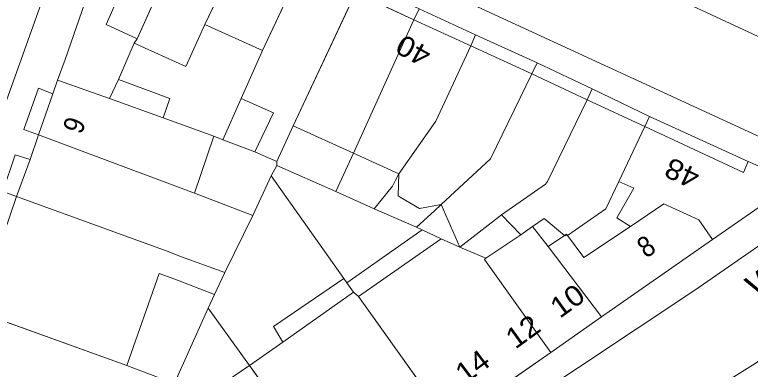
# Model space of a CAD drawing. Extents: x 528790 to 529292, y 179350 to 179856.
# Drawn here: x 529183.9 to 529237.6, y 179393.9 to 179419.8 of the extents above; entities that cross this region are included whole.
import ezdxf

# ---------------------------------------------------------------- set-up
doc = ezdxf.new("R2010")
doc.units = 0
doc.header["$LTSCALE"] = 0.6
doc.layers.add('1', color=7, linetype='Continuous', lineweight=13)
doc.layers.add('2', color=7, linetype='Continuous', lineweight=13)
doc.layers.add('5', color=7, linetype='Continuous')

msp = doc.modelspace()

# ---------------------------------------------------------------- linework, layer by layer
at = {"layer": '1'}
for points in [[(529152.592, 179458.708), (529152.53, 179458.27), (529152.737, 179457.756), (529153.247, 179457.24), (529154.075, 179456.846), (529157.2, 179455.4), (529168.6, 179450.1), (529184.6, 179442.9), (529186.46, 179442.05), (529193.12, 179438.98), (529195.7, 179437.8), (529210.8, 179430.8), (529226.95, 179423.45), (529240.8, 179417)], [(529242.05, 179409.15), (529191.35, 179432.55)], [(529181.6, 179428.5), (529176.4, 179414.3), (529171.5, 179401.3), (529167.35, 179390.15), (529162.35, 179376.4), (529162.05, 179375.9), (529161.9, 179375.7), (529161.6, 179375.55), (529161.25, 179375.45), (529169.115, 179372.981), (529169.121, 179373.036), (529169.129, 179373.091), (529169.131, 179373.129), (529169.2, 179374.196), (529169.204, 179374.262), (529169.205, 179374.273), (529189.9, 179432.1)], [(529189.9, 179432.1), (529169.205, 179374.273)], [(529183.1, 179403.9), (529184, 179406.55), (529183, 179406.9), (529183.9, 179409.6), (529185, 179409.25), (529185.6, 179411.05), (529184.55, 179411.45), (529185.6, 179414.45), (529186.65, 179414.05), (529187, 179415.05), (529187.55, 179416.55), (529189.4, 179421.9)], [(529213.4, 179420.25), (529217.5, 179418.35), (529222, 179416.3), (529226, 179414.4), (529230.2, 179412.4), (529237.4, 179409.1), (529239.25, 179408.3)], [(529239.4, 179406.6), (529234.8, 179403.4), (529226.7, 179397.75), (529223, 179395.15), (529215.55, 179390), (529215.2, 179389.8), (529207.9, 179384.7), (529204, 179382.05), (529200.3, 179379.5), (529196.4, 179376.8), (529193, 179374.5), (529189.15, 179371.8), (529183.05, 179370.6)], [(529195.35, 179374.3), (529233.5, 179399.7), (529242.15, 179405.7)], [(529242.15, 179405.7), (529233.5, 179399.7), (529195.35, 179374.3)], [(529237.9, 179394.35), (529233.9, 179391.85)], [(529233.9, 179391.85), (529237.9, 179394.35)]]:
    msp.add_lwpolyline(points, dxfattribs=at)
for points in [[(529190.2, 179432.45), (529190.55, 179432.55), (529190.8, 179432.65), (529191.05, 179432.65), (529191.35, 179432.55), (529242.05, 179409.15), (529242.35, 179408.85), (529242.6, 179408.15), (529250, 179413.05), (529240.8, 179417), (529226.95, 179423.45), (529210.8, 179430.8), (529195.7, 179437.8), (529193.12, 179438.98)], [(529192.8, 179418.05), (529196.8, 179427), (529192, 179429.25), (529189.4, 179421.9), (529191.4, 179421.05), (529190.55, 179419.1)], [(529192.6, 179417.75), (529196.35, 179416.05), (529197.75, 179419.1), (529200.65, 179425.2), (529196.8, 179427), (529192.8, 179418.05)], [(529201.95, 179417.2), (529204.8, 179423.3), (529200.65, 179425.2), (529197.75, 179419.1)], [(529208.75, 179421.45), (529204.8, 179423.3), (529201.95, 179417.2), (529200.4, 179413.7), (529202.75, 179412.65), (529201.4, 179409.8), (529203, 179409.1), (529204.2, 179411.7)], [(529208.75, 179421.45), (529213, 179419.45), (529213.4, 179420.25), (529209.15, 179422.25)], [(529191.45, 179415.1), (529192.6, 179417.75), (529192.8, 179418.05), (529190.55, 179419.1), (529191.4, 179421.05), (529189.4, 179421.9), (529187.55, 179416.55), (529187, 179415.05), (529190.8, 179413.7)], [(529204.2, 179411.7), (529208.6, 179409.7), (529213, 179419.45), (529208.75, 179421.45)], [(529213.4, 179420.25), (529213, 179419.45), (529217.15, 179417.55), (529217.5, 179418.35)], [(529211.9, 179408.2), (529214.6, 179412.05), (529217.15, 179417.55), (529213, 179419.45), (529208.6, 179409.7)], [(529199.07, 179410.69), (529200.4, 179413.7), (529201.95, 179417.2), (529197.75, 179419.1), (529196.35, 179416.05), (529192.6, 179417.75), (529191.45, 179415.1), (529195.2, 179413.7), (529194.95, 179413), (529194.7, 179412.3), (529198.4, 179410.95)], [(529217.15, 179417.55), (529221.6, 179415.5), (529222, 179416.3), (529217.5, 179418.35)], [(529215, 179405.95), (529218.6, 179409.3), (529221.6, 179415.5), (529217.15, 179417.55), (529214.6, 179412.05), (529211.9, 179408.2), (529211.852, 179406.591), (529211.935, 179406.541), (529212.004, 179406.5), (529213.41, 179405.659)], [(529226, 179414.4), (529222, 179416.3), (529221.6, 179415.5), (529225.65, 179413.6)], [(529219.4, 179405.2), (529222.6, 179407.45), (529222.75, 179407.65), (529225.65, 179413.6), (529221.6, 179415.5), (529218.6, 179409.3), (529215, 179405.95), (529216.35, 179402.85)], [(529187, 179415.05), (529186.65, 179414.05), (529185.6, 179411.05), (529197, 179406.8), (529198.4, 179410.95), (529194.7, 179412.3), (529190.8, 179413.7)], [(529191.45, 179415.1), (529190.8, 179413.7), (529194.7, 179412.3), (529194.95, 179413), (529195.2, 179413.7)], [(529186.65, 179414.05), (529185.6, 179414.45), (529184.55, 179411.45), (529185.6, 179411.05)], [(529226, 179414.4), (529225.65, 179413.6), (529229.85, 179411.65), (529230.2, 179412.4)], [(529202.75, 179412.65), (529200.4, 179413.7), (529199.07, 179410.69), (529201.4, 179409.8)], [(529221.65, 179404.35), (529222.5, 179404.95), (529224, 179403.7), (529224.15, 179403.8), (529224.2, 179403.7), (529227, 179405.65), (529227.95, 179407.65), (529229.85, 179411.65), (529225.65, 179413.6), (529222.75, 179407.65), (529222.6, 179407.45), (529219.4, 179405.2), (529220.8, 179403.75)], [(529237.4, 179409.1), (529230.2, 179412.4), (529229.85, 179411.65), (529237.05, 179408.3)], [(529203, 179409.1), (529203, 179408.8), (529207.3, 179406.9), (529208.6, 179409.7), (529204.2, 179411.7)], [(529237.4, 179409.1), (529237.05, 179408.3), (529229.85, 179411.65), (529227.95, 179407.65), (529229.05, 179407.15), (529227.8, 179405), (529228.8, 179404.35), (529231.25, 179406), (529233.8, 179404.85), (529234.8, 179403.4), (529239.4, 179406.6), (529239.25, 179408.3)], [(529199.2, 179401), (529201.25, 179405.15), (529197, 179406.8), (529185.6, 179411.05), (529185, 179409.25), (529184, 179406.55), (529195, 179402.55), (529196.05, 179402.15)], [(529202.6, 179408.05), (529203, 179408.8), (529203, 179409.1), (529201.4, 179409.8), (529199.07, 179410.69), (529198.4, 179410.95), (529197, 179406.8), (529201.25, 179405.15)], [(529185, 179409.25), (529183.9, 179409.6), (529183, 179406.9), (529184, 179406.55)], [(529211.45, 179407.3), (529211.668, 179407.736), (529211.9, 179408.2), (529208.6, 179409.7), (529207.3, 179406.9), (529210.1, 179405.65)], [(529208.1, 179400.25), (529213.6, 179404.1), (529213.2, 179404.3), (529210.1, 179405.65), (529207.3, 179406.9), (529203, 179408.8), (529202.6, 179408.05), (529207.9, 179400.55)], [(529213.2, 179404.3), (529214.504, 179405.495), (529215, 179405.95), (529213.41, 179405.659), (529212.004, 179406.5), (529211.935, 179406.541), (529211.852, 179406.591), (529211.9, 179408.2), (529211.668, 179407.736), (529211.45, 179407.3), (529210.1, 179405.65)], [(529203.45, 179395.9), (529202.75, 179397.05), (529205.29, 179398.78), (529207.9, 179400.55), (529202.6, 179408.05), (529201.25, 179405.15), (529199.2, 179401), (529198.45, 179399.4), (529198, 179398.4), (529201, 179394.2)], [(529228.8, 179404.35), (529227.8, 179405), (529229.05, 179407.15), (529227.95, 179407.65), (529227, 179405.65), (529224.2, 179403.7), (529225.4, 179402.1)], [(529192.05, 179394.2), (529194.427, 179400.927), (529195.55, 179400.501), (529198.45, 179399.4), (529199.2, 179401), (529196.05, 179402.15), (529195, 179402.55), (529184, 179406.55), (529183.1, 179403.9), (529181.1, 179398.15)], [(529216.35, 179402.85), (529215, 179405.95), (529214.504, 179405.495), (529213.2, 179404.3), (529213.6, 179404.1), (529215, 179403.45)], [(529226.7, 179397.75), (529234.8, 179403.4), (529233.8, 179404.85), (529231.25, 179406), (529228.8, 179404.35), (529225.4, 179402.1), (529224.2, 179403.7), (529224.1, 179403.67), (529224, 179403.7), (529222.8, 179402.9)], [(529218.25, 179402.05), (529220.8, 179403.75), (529219.4, 179405.2), (529216.35, 179402.85)], [(529222.8, 179402.9), (529224, 179403.7), (529222.5, 179404.95), (529221.65, 179404.35)], [(529208.6, 179399.55), (529208.95, 179399.25), (529215, 179403.45), (529213.6, 179404.1), (529208.1, 179400.25)], [(529221.65, 179404.35), (529220.8, 179403.75), (529218.25, 179402.05), (529218.15, 179401.95), (529223, 179395.15), (529226.7, 179397.75), (529222.8, 179402.9)], [(529208.95, 179399.25), (529215.55, 179390), (529223, 179395.15), (529218.15, 179401.95), (529218.25, 179402.05), (529216.35, 179402.85), (529215, 179403.45)], [(529224.2, 179403.7), (529224.15, 179403.8), (529224, 179403.7), (529224.1, 179403.67)], [(529195.75, 179393.4), (529198, 179398.4), (529198.45, 179399.4), (529195.55, 179400.501), (529194.427, 179400.927), (529192.05, 179394.2), (529195.5, 179392.9)], [(529208.1, 179400.25), (529207.9, 179400.55), (529205.29, 179398.78), (529202.75, 179397.05), (529203.45, 179395.9), (529208.6, 179399.55)], [(529215.55, 179390), (529208.95, 179399.25), (529208.6, 179399.55), (529203.45, 179395.9), (529201, 179394.2), (529207.9, 179384.7), (529215.2, 179389.8)], [(529194.322, 179390.628), (529195.5, 179392.9), (529192.05, 179394.2), (529181.1, 179398.15), (529180.5, 179396.45), (529179.5, 179393.65), (529189, 179390.3), (529193.4, 179388.85)], [(529200.033, 179391.89), (529199.25, 179393), (529201, 179394.2), (529198, 179398.4), (529195.75, 179393.4), (529197.901, 179390.415)], [(529207.9, 179384.7), (529201, 179394.2), (529199.25, 179393), (529200.033, 179391.89), (529197.901, 179390.415), (529198.2, 179390), (529199.35, 179388.55), (529200.019, 179387.614), (529204, 179382.05)]]:
    msp.add_lwpolyline(points, close=True, dxfattribs=at)
at = {"layer": '2'}
for p, q in [((529196.8, 179427), (529192.8, 179418.05)), ((529200.65, 179425.2), (529197.75, 179419.1)), ((529204.8, 179423.3), (529201.95, 179417.2)), ((529208.75, 179421.45), (529204.2, 179411.7)), ((529208.75, 179421.45), (529213, 179419.45)), ((529213.4, 179420.25), (529213, 179419.45)), ((529217.5, 179418.35), (529213.4, 179420.25)), ((529213, 179419.45), (529208.6, 179409.7)), ((529213, 179419.45), (529217.15, 179417.55)), ((529197.75, 179419.1), (529201.95, 179417.2)), ((529217.5, 179418.35), (529217.15, 179417.55)), ((529222, 179416.3), (529217.5, 179418.35)), ((529192.8, 179418.05), (529192.6, 179417.75)), ((529192.6, 179417.75), (529191.45, 179415.1)), ((529217.15, 179417.55), (529221.6, 179415.5)), ((529201.95, 179417.2), (529200.4, 179413.7)), ((529222, 179416.3), (529221.6, 179415.5)), ((529226, 179414.4), (529222, 179416.3)), ((529221.6, 179415.5), (529218.6, 179409.3)), ((529221.6, 179415.5), (529225.65, 179413.6)), ((529187, 179415.05), (529186.65, 179414.05)), ((529187, 179415.05), (529190.8, 179413.7)), ((529191.45, 179415.1), (529190.8, 179413.7)), ((529226, 179414.4), (529225.65, 179413.6)), ((529230.2, 179412.4), (529226, 179414.4)), ((529186.65, 179414.05), (529185.6, 179411.05)), ((529190.8, 179413.7), (529194.7, 179412.3)), ((529200.4, 179413.7), (529199.07, 179410.69)), ((529225.65, 179413.6), (529229.85, 179411.65)), ((529194.7, 179412.3), (529198.4, 179410.95)), ((529230.2, 179412.4), (529229.85, 179411.65)), ((529237.4, 179409.1), (529230.2, 179412.4)), ((529203, 179409.1), (529204.2, 179411.7)), ((529204.2, 179411.7), (529208.6, 179409.7)), ((529229.85, 179411.65), (529227.95, 179407.65)), ((529185.6, 179411.05), (529185, 179409.25)), ((529185.6, 179411.05), (529197, 179406.8)), ((529198.4, 179410.95), (529197, 179406.8)), ((529199.07, 179410.69), (529198.4, 179410.95)), ((529201.4, 179409.8), (529199.07, 179410.69)), ((529201.4, 179409.8), (529203, 179409.1)), ((529185, 179409.25), (529184, 179406.55)), ((529208.6, 179409.7), (529207.3, 179406.9)), ((529208.6, 179409.7), (529211.9, 179408.2)), ((529218.6, 179409.3), (529215, 179405.95)), ((529203, 179408.8), (529202.6, 179408.05)), ((529203, 179409.1), (529203, 179408.8)), ((529203, 179408.8), (529207.3, 179406.9)), ((529202.6, 179408.05), (529201.25, 179405.15)), ((529202.6, 179408.05), (529207.9, 179400.55)), ((529222.6, 179407.45), (529219.4, 179405.2)), ((529184, 179406.55), (529183.1, 179403.9)), ((529197, 179406.8), (529201.25, 179405.15)), ((529207.3, 179406.9), (529210.1, 179405.65)), ((529210.1, 179405.65), (529213.2, 179404.3)), ((529215, 179405.95), (529216.35, 179402.85)), ((529201.25, 179405.15), (529199.2, 179401)), ((529219.4, 179405.2), (529216.35, 179402.85)), ((529219.4, 179405.2), (529220.8, 179403.75)), ((529213.6, 179404.1), (529208.1, 179400.25)), ((529213.2, 179404.3), (529213.6, 179404.1)), ((529213.6, 179404.1), (529215, 179403.45)), ((529220.8, 179403.75), (529221.65, 179404.35)), ((529221.65, 179404.35), (529222.8, 179402.9)), ((529208.95, 179399.25), (529215, 179403.45)), ((529215, 179403.45), (529216.35, 179402.85)), ((529218.25, 179402.05), (529220.8, 179403.75)), ((529224, 179403.7), (529222.8, 179402.9)), ((529234.8, 179403.4), (529226.7, 179397.75)), ((529216.35, 179402.85), (529218.25, 179402.05)), ((529222.8, 179402.9), (529226.7, 179397.75)), ((529199.2, 179401), (529198.45, 179399.4)), ((529207.9, 179400.55), (529208.1, 179400.25)), ((529208.1, 179400.25), (529208.6, 179399.55)), ((529198.45, 179399.4), (529198, 179398.4)), ((529203.45, 179395.9), (529208.6, 179399.55)), ((529208.6, 179399.55), (529208.95, 179399.25)), ((529208.95, 179399.25), (529215.55, 179390)), ((529181.1, 179398.15), (529192.05, 179394.2)), ((529198, 179398.4), (529195.75, 179393.4)), ((529198, 179398.4), (529201, 179394.2)), ((529226.7, 179397.75), (529223, 179395.15)), ((529203.45, 179395.9), (529202.75, 179397.05)), ((529201, 179394.2), (529203.45, 179395.9)), ((529223, 179395.15), (529215.55, 179390)), ((529192.05, 179394.2), (529195.5, 179392.9)), ((529201, 179394.2), (529207.9, 179384.7))]:
    msp.add_line(p, q, dxfattribs=at)
for points in [[(529250, 179413.05), (529240.8, 179417), (529226.95, 179423.45), (529210.8, 179430.8), (529195.7, 179437.8), (529193.12, 179438.98)], [(529190.2, 179432.45), (529189.9, 179432.1), (529169.205, 179374.273), (529169.204, 179374.262), (529169.2, 179374.196), (529169.131, 179373.129), (529169.129, 179373.091), (529169.121, 179373.036), (529169.115, 179372.981)], [(529242.6, 179408.15), (529242.35, 179408.85), (529242.05, 179409.15), (529191.35, 179432.55), (529191.05, 179432.65), (529190.8, 179432.65), (529190.55, 179432.55), (529190.2, 179432.45)], [(529189.4, 179421.9), (529187.55, 179416.55), (529187, 179415.05)], [(529189.4, 179421.9), (529191.4, 179421.05), (529190.55, 179419.1), (529192.8, 179418.05)], [(529192.6, 179417.75), (529196.35, 179416.05), (529197.75, 179419.1)], [(529217.15, 179417.55), (529214.6, 179412.05), (529211.9, 179408.2)], [(529191.45, 179415.1), (529195.2, 179413.7), (529194.95, 179413), (529194.7, 179412.3)], [(529185.6, 179411.05), (529184.55, 179411.45), (529185.6, 179414.45), (529186.65, 179414.05)], [(529200.4, 179413.7), (529202.75, 179412.65), (529201.4, 179409.8)], [(529225.65, 179413.6), (529222.75, 179407.65), (529222.6, 179407.45)], [(529229.85, 179411.65), (529237.05, 179408.3), (529237.4, 179409.1)], [(529184, 179406.55), (529183, 179406.9), (529183.9, 179409.6), (529185, 179409.25)], [(529237.4, 179409.1), (529239.25, 179408.3), (529239.4, 179406.6), (529234.8, 179403.4)], [(529210.1, 179405.65), (529211.45, 179407.3), (529211.668, 179407.736), (529211.9, 179408.2)], [(529211.9, 179408.2), (529211.852, 179406.591), (529211.935, 179406.541), (529212.004, 179406.5), (529213.41, 179405.659), (529215, 179405.95)], [(529224.2, 179403.7), (529227, 179405.65), (529227.95, 179407.65)], [(529227.95, 179407.65), (529229.05, 179407.15), (529227.8, 179405), (529228.8, 179404.35)], [(529184, 179406.55), (529195, 179402.55), (529196.05, 179402.15), (529199.2, 179401)], [(529195.35, 179374.3), (529233.5, 179399.7), (529242.15, 179405.7)], [(529213.2, 179404.3), (529214.504, 179405.495), (529215, 179405.95)], [(529234.8, 179403.4), (529233.8, 179404.85), (529231.25, 179406), (529228.8, 179404.35)], [(529221.65, 179404.35), (529222.5, 179404.95), (529224, 179403.7)], [(529228.8, 179404.35), (529225.4, 179402.1), (529224.2, 179403.7)], [(529224.2, 179403.7), (529224.15, 179403.8), (529224, 179403.7)], [(529224, 179403.7), (529224.1, 179403.67), (529224.2, 179403.7)], [(529191.5, 179360.5), (529191.8, 179361.55), (529192.35, 179362.15), (529211, 179377.8), (529214.55, 179380), (529220, 179383.1), (529228.4, 179388.2), (529233.9, 179391.85), (529237.9, 179394.35), (529249.7, 179402.75)], [(529223, 179395.15), (529218.15, 179401.95), (529218.25, 179402.05)], [(529198.45, 179399.4), (529195.55, 179400.501), (529194.427, 179400.927), (529192.05, 179394.2)], [(529202.75, 179397.05), (529205.29, 179398.78), (529207.9, 179400.55)], [(529197.901, 179390.415), (529200.033, 179391.89), (529199.25, 179393), (529201, 179394.2)]]:
    msp.add_lwpolyline(points, dxfattribs=at)

# ---------------------------------------------------------------- texts
at = {"layer": '5'}
for s, height, rotation, width, p in [('40', 1.5, 151, 1.1, (529214.4, 179417.25)), ('6', 1.5, 249, 0.9, (529187.7, 179412.5)), ('48', 1.5, 155, 1.1, (529234, 179408.4)), ('WILFRED', 1.75, 34, 1.1, (529238, 179399)), ('8', 1.5, 34, 0.9, (529229.95, 179402)), ('10', 1.5, 36, 1.1, (529223.65, 179397.6)), ('12', 1.5, 36, 1.1, (529220.4, 179395.35)), ('14', 1.5, 37, 1.1, (529216.75, 179392.8))]:
    msp.add_text(s, height=height, rotation=rotation, dxfattribs=dict(at, width=width)).set_placement(p)

doc.saveas('drawing.dxf')
